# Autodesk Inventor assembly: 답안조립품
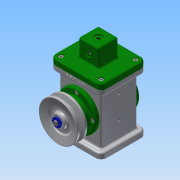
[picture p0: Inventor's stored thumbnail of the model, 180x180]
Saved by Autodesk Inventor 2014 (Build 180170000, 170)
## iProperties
Created: 2017-08
Part Number: 답안조립품
Document SubType Name: Assembly
Designer: 학생용
Author: 학생용
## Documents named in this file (18)
- C:\Users\net\Desktop\470807V1001\답안조립품.iam
- C:\Users\net\Desktop\470807V1001\본체.ipt
- C:\Users\net\Desktop\470807V1001\편심축.ipt
- C:\Users\net\Desktop\470807V1001\베어링 17 x 40 x 12.ipt
- C:\Users\net\Desktop\470807V1001\뒤커버.ipt
- C:\Users\net\Desktop\470807V1001\볼트 M4 x 8.ipt
- C:\Users\net\Desktop\470807V1001\앞커버.ipt
- C:\Users\net\Desktop\470807V1001\오일 실 17 30 8.ipt
- C:\Users\net\Desktop\470807V1001\키 4 x 4 x 12.ipt
- C:\Users\net\Desktop\470807V1001\V-벨트풀리.ipt
- C:\Users\net\Desktop\470807V1001\와셔 4x16.ipt
- C:\Users\net\Desktop\470807V1001\볼트 M4 x 10.ipt
- C:\Users\net\Desktop\470807V1001\링크.ipt
- C:\Users\net\Desktop\470807V1001\클레비스 핀 6 x 22.ipt
- 클레비스 핀 6 x 22.ipt
- C:\Users\net\Desktop\470807V1001\슬라이더.ipt
- C:\Users\net\Desktop\470807V1001\덮개.ipt
- C:\Users\net\Desktop\470807V1001\E-링.ipt
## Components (2 placed, 2 different names)
1. V-벨트풀리:1
2. E-링:1
